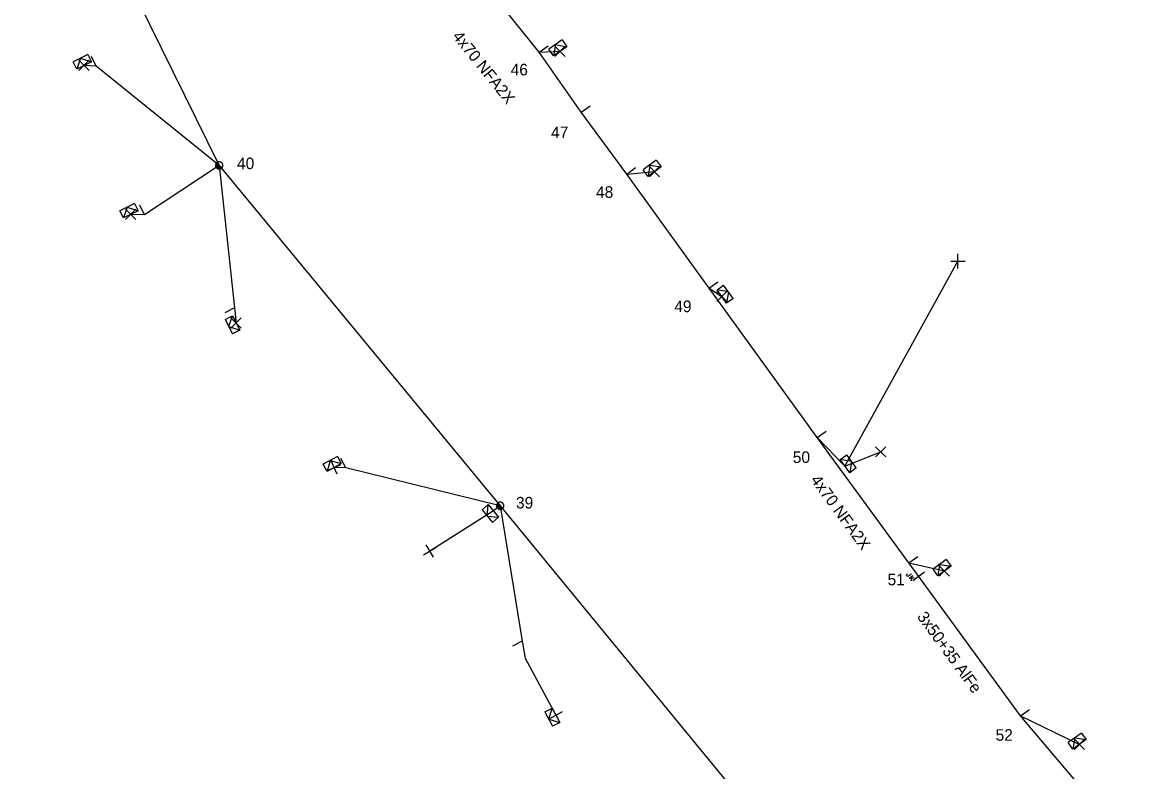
# Model space of a CAD drawing. Extents: x -536149 to -535465, y -1201639 to -1201298.
# Drawn here: x -535704.3 to -535608.3, y -1201422.6 to -1201357.9 of the extents above; entities that cross this region are included whole.
import ezdxf

# ---------------------------------------------------------------- set-up
doc = ezdxf.new("R2010")
doc.units = 0
for name, color, linetype in [('Vrstva 1', 7, 'Continuous'), ('Vrstva 13', 7, 'Continuous'), ('Vrstva 14', 7, 'Continuous'), ('Vrstva 15', 7, 'Continuous'), ('Vrstva 18', 7, 'Continuous'), ('Vrstva 2', 7, 'Continuous'), ('Vrstva 31', 7, 'Continuous'), ('Vrstva 34', 7, 'Continuous'), ('Vrstva 50', 7, 'Continuous'), ('Vrstva 51', 7, 'Continuous'), ('Vrstva 54', 7, 'Continuous'), ('Vrstva 59', 7, 'Continuous'), ('Vrstva 8', 7, 'Continuous'), ('Vrstva 9', 7, 'Continuous')]:
    doc.layers.add(name, color=color, linetype=linetype)

# ---------------------------------------------------------------- blocks, each defined once
blk = doc.blocks.new('NN440')
at = {"layer": 'Vrstva 2'}
for points in [[(0.63, 0), (0.63, 0.06), (0.62, 0.13), (0.6, 0.19), (0.58, 0.25), (0.55, 0.31), (0.51, 0.37), (0.47, 0.42), (0.42, 0.46), (0.37, 0.51), (0.32, 0.54), (0.26, 0.57), (0.2, 0.59), (0.13, 0.61), (0.07, 0.62), (0, 0.63), (-0.06, 0.62), (-0.13, 0.61), (-0.19, 0.59), (-0.26, 0.57), (-0.31, 0.54), (-0.37, 0.51), (-0.42, 0.46), (-0.47, 0.42), (-0.51, 0.37), (-0.54, 0.31), (-0.57, 0.25), (-0.6, 0.19), (-0.62, 0.13), (-0.63, 0.06), (-0.63, 0), (-0.63, -0.07), (-0.62, -0.14), (-0.6, -0.2), (-0.57, -0.26), (-0.54, -0.32), (-0.51, -0.37), (-0.47, -0.43), (-0.42, -0.47), (-0.37, -0.51), (-0.31, -0.55), (-0.26, -0.58), (-0.19, -0.6), (-0.13, -0.62), (-0.06, -0.63), (0, -0.63), (0.07, -0.63), (0.13, -0.62), (0.2, -0.6), (0.26, -0.58), (0.32, -0.55), (0.37, -0.51), (0.42, -0.47), (0.47, -0.43), (0.51, -0.37), (0.55, -0.32), (0.58, -0.26), (0.6, -0.2), (0.62, -0.14), (0.63, -0.07), (0.63, 0)], [(-0.63, 0), (0.63, 0)], [(-0.6, -0.18), (0.57, -0.18)], [(-0.51, -0.32), (0.5, -0.32)], [(-0.37, -0.47), (0.35, -0.47)]]:
    blk.add_lwpolyline(points, dxfattribs=at)
blk = doc.blocks.new('NN840')
at = {"layer": 'Vrstva 15'}
for points in [[(0.003, 0.619), (0.003, -0.631)], [(-0.745, -0.71), (-0.745, -0.66)], [(-0.73, -0.764), (-0.745, -0.71)], [(-0.657, -0.798), (-0.73, -0.764)], [(-0.627, -0.798), (-0.657, -0.798)], [(-0.558, -0.764), (-0.627, -0.798)], [(-0.538, -0.71), (-0.558, -0.764)], [(-0.538, -0.385), (-0.538, -0.71)], [(-0.332, -0.385), (-0.332, -0.798)], [(-0.332, -0.641), (-0.125, -0.385)], [(-0.263, -0.557), (-0.091, -0.798)]]:
    blk.add_lwpolyline(points, dxfattribs=at)
blk = doc.blocks.new('NN800')
at = {"layer": 'Vrstva 1'}
for points in [[(-0.442, 0.442), (0.442, -0.442)], [(-0.442, -0.442), (0.442, 0.442)]]:
    blk.add_lwpolyline(points, dxfattribs=at)
blk = doc.blocks.new('NN630')
at = {"layer": 'Vrstva 9'}
for points in [[(-0.003, -0.7), (-0.703, 0)], [(-0.703, -0.7), (-0.703, 0), (0.697, 0), (0.697, -0.7)], [(-0.703, -0.7), (0.697, -0.7)], [(-0.003, -0.7), (0.697, 0)]]:
    blk.add_lwpolyline(points, dxfattribs=at)
blk = doc.blocks.new('NN510')
at = {"layer": 'Vrstva 2'}
blk.add_lwpolyline([(0.001, 0.002), (0.001, 0.939)], dxfattribs=at)

msp = doc.modelspace()

# ---------------------------------------------------------------- linework, layer by layer
at = {"layer": 'Vrstva 1'}
for points in [[(-535704.28, -1201335.78), (-535687.29, -1201370.27), (-535663.05, -1201399.63), (-535635.32, -1201433.41), (-535614.862, -1201457.774), (-535589.24, -1201487.744), (-535570.255, -1201520.699), (-535562.055, -1201543.241)], [(-535566.21, -1201489.133), (-535573.362, -1201479.314), (-535581.292, -1201468.256), (-535583.925, -1201464.639), (-535590.303, -1201455.917), (-535602.568, -1201439.045), (-535607.499, -1201430.342), (-535618.17, -1201417.757), (-535627.799, -1201404.564)]]:
    msp.add_lwpolyline(points, dxfattribs=at)
at = {"layer": 'Vrstva 50'}
msp.add_lwpolyline([(-535627.799, -1201404.564), (-535635.707, -1201393.748), (-535645.039, -1201380.866), (-535652.143, -1201371.008), (-535656.064, -1201365.681), (-535659.686, -1201360.49), (-535664.84, -1201354.078), (-535664.841, -1201354.077)], dxfattribs=at)
at = {"layer": 'Vrstva 54'}
for points in [[(-535659.686, -1201360.49), (-535657.893, -1201360.419)], [(-535687.29, -1201370.27), (-535693.734, -1201374.54), (-535694.922, -1201374.495)], [(-535652.143, -1201371.008), (-535649.743, -1201370.8)], [(-535645.039, -1201380.866), (-535643.94, -1201381.576)], [(-535663.05, -1201399.63), (-535663.633, -1201400.077)], [(-535618.17, -1201417.757), (-535613.086, -1201420.218)]]:
    msp.add_lwpolyline(points, dxfattribs=at)
at = {"layer": 'Vrstva 59'}
for points in [[(-535633.32, -1201396.213), (-535623.573, -1201378.533)], [(-535633.32, -1201396.213), (-535630.235, -1201394.972)], [(-535663.633, -1201400.077), (-535669.128, -1201403.532)]]:
    msp.add_lwpolyline(points, dxfattribs=at)
at = {"layer": 'Vrstva 8'}
for points in [[(-535687.29, -1201370.27), (-535697.905, -1201361.707), (-535698.947, -1201361.642)], [(-535687.29, -1201370.27), (-535685.964, -1201382.55), (-535685.834, -1201383.866)], [(-535635.707, -1201393.748), (-535633.32, -1201396.213)], [(-535663.05, -1201399.63), (-535676.358, -1201396.359), (-535677.377, -1201396.325)], [(-535663.05, -1201399.63), (-535661.159, -1201411.303), (-535660.891, -1201412.779), (-535658.249, -1201417.705)], [(-535627.799, -1201404.564), (-535624.739, -1201405.25)]]:
    msp.add_lwpolyline(points, dxfattribs=at)

# ---------------------------------------------------------------- block references
at = {"layer": 'Vrstva 13'}
for p, rotation in [((-535659.687, -1201360.49), -54.066469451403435), ((-535697.905, -1201361.708), 26.21569160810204), ((-535656.065, -1201365.681), -54.06646942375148), ((-535652.144, -1201371.008), -54.066469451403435), ((-535693.734, -1201374.54), 26.002647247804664), ((-535645.039, -1201380.866), -54.21398046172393), ((-535685.964, -1201382.551), 116.5570527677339), ((-535635.707, -1201393.748), -54.21398048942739), ((-535676.358, -1201396.359), 29.05460272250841), ((-535627.799, -1201404.564), -54.2139805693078), ((-535661.158, -1201411.303), 118.19804171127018), ((-535618.17, -1201417.757), -54.21398054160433)]:
    msp.add_blockref('NN510', p, dxfattribs=dict(at, rotation=rotation))
at = {"layer": 'Vrstva 13', "xscale": 0.5, "yscale": 0.5}
for p, rotation in [((-535687.29, -1201370.27), -50.48374165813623), ((-535663.05, -1201399.63), -50.57305274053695)]:
    msp.add_blockref('NN440', p, dxfattribs=dict(at, rotation=rotation))
at = {"layer": 'Vrstva 18', "rotation": -53.87591111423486}
msp.add_blockref('NN840', (-535626.951, -1201405.726), dxfattribs=at)
at = {"layer": 'Vrstva 31'}
for p, rotation in [((-535657.893, -1201360.419), -145.71327212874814), ((-535698.947, -1201361.642), -153.78551115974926), ((-535649.743, -1201370.8), -143.6395471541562), ((-535694.922, -1201374.495), -154.00398898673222), ((-535643.94, -1201381.576), 125.86873882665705), ((-535685.834, -1201383.866), -63.40905549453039), ((-535677.377, -1201396.325), -151.16610838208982), ((-535633.32, -1201396.213), 126.10046113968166), ((-535663.633, -1201400.076), -50.60113056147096), ((-535624.739, -1201405.25), -143.7744472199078), ((-535658.249, -1201417.705), -61.818925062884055), ((-535613.086, -1201420.218), -143.917683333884)]:
    msp.add_blockref('NN630', p, dxfattribs=dict(at, rotation=rotation))
at = {"layer": 'Vrstva 34'}
for p in [(-535657.893, -1201360.419), (-535698.947, -1201361.642), (-535649.743, -1201370.8), (-535694.922, -1201374.495), (-535643.94, -1201381.576), (-535685.834, -1201383.866), (-535630.235, -1201394.972), (-535624.739, -1201405.25), (-535613.086, -1201420.218)]:
    msp.add_blockref('NN800', p, dxfattribs=at)
for p, rotation in [((-535623.573, -1201378.533), 44.999999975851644), ((-535677.377, -1201396.325), 70.03070835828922), ((-535669.128, -1201403.532), 75.7294194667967), ((-535658.249, -1201417.705), 164.06395827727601)]:
    msp.add_blockref('NN800', p, dxfattribs=dict(at, rotation=rotation))

# ---------------------------------------------------------------- texts
at = {"layer": 'Vrstva 14'}
for s, p in [('46', (-535662.153, -1201362.502)), ('47', (-535658.664, -1201367.915)), ('40', (-535685.756, -1201370.591)), ('48', (-535654.789, -1201373.065)), ('49', (-535648.039, -1201382.923)), ('50', (-535637.818, -1201395.938)), ('39', (-535661.693, -1201399.863)), ('51', (-535629.644, -1201406.487)), ('52', (-535620.326, -1201419.903))]:
    msp.add_text(s, height=1, dxfattribs=at).set_placement(p)
at = {"layer": 'Vrstva 2'}
msp.add_text('3x50+35 AlFe', height=1, rotation=306.124, dxfattribs=at).set_placement((-535627.143, -1201409.205))
at = {"layer": 'Vrstva 51'}
for rotation, p in [(308.793, (-535667.228, -1201359.156)), (306.172, (-535636.326, -1201397.415))]:
    msp.add_text('4x70 NFA2X', height=1, rotation=rotation, dxfattribs=at).set_placement(p)

doc.saveas('drawing.dxf')
